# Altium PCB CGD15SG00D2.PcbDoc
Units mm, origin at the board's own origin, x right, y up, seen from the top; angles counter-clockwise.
Board outline 47.62 x 17.78 mm, 4 copper layers (TOP, INNER1, INNER2, BOTTOM), stack 1.557 mm thick; 46 components, 23 nets, 113 pads, 36 vias.
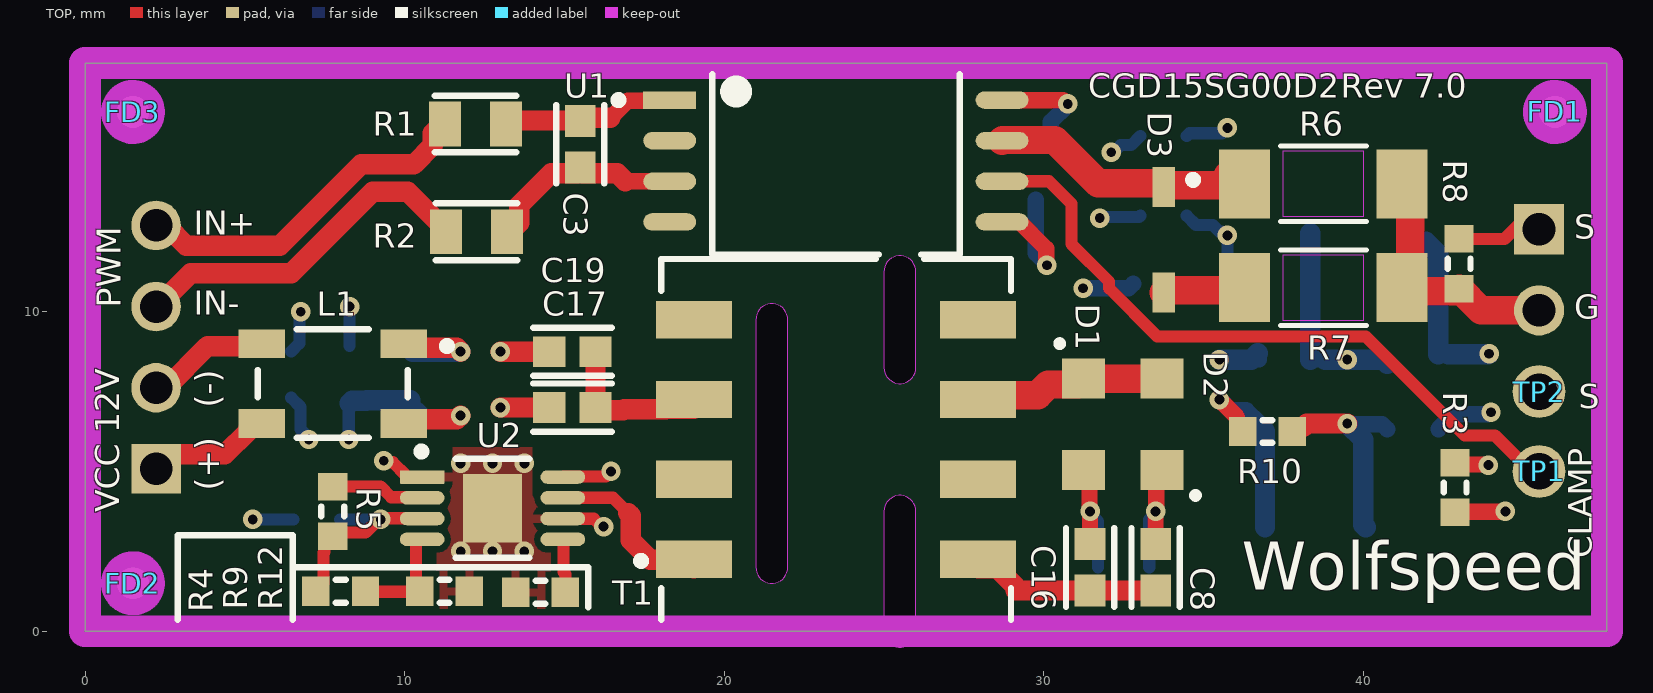
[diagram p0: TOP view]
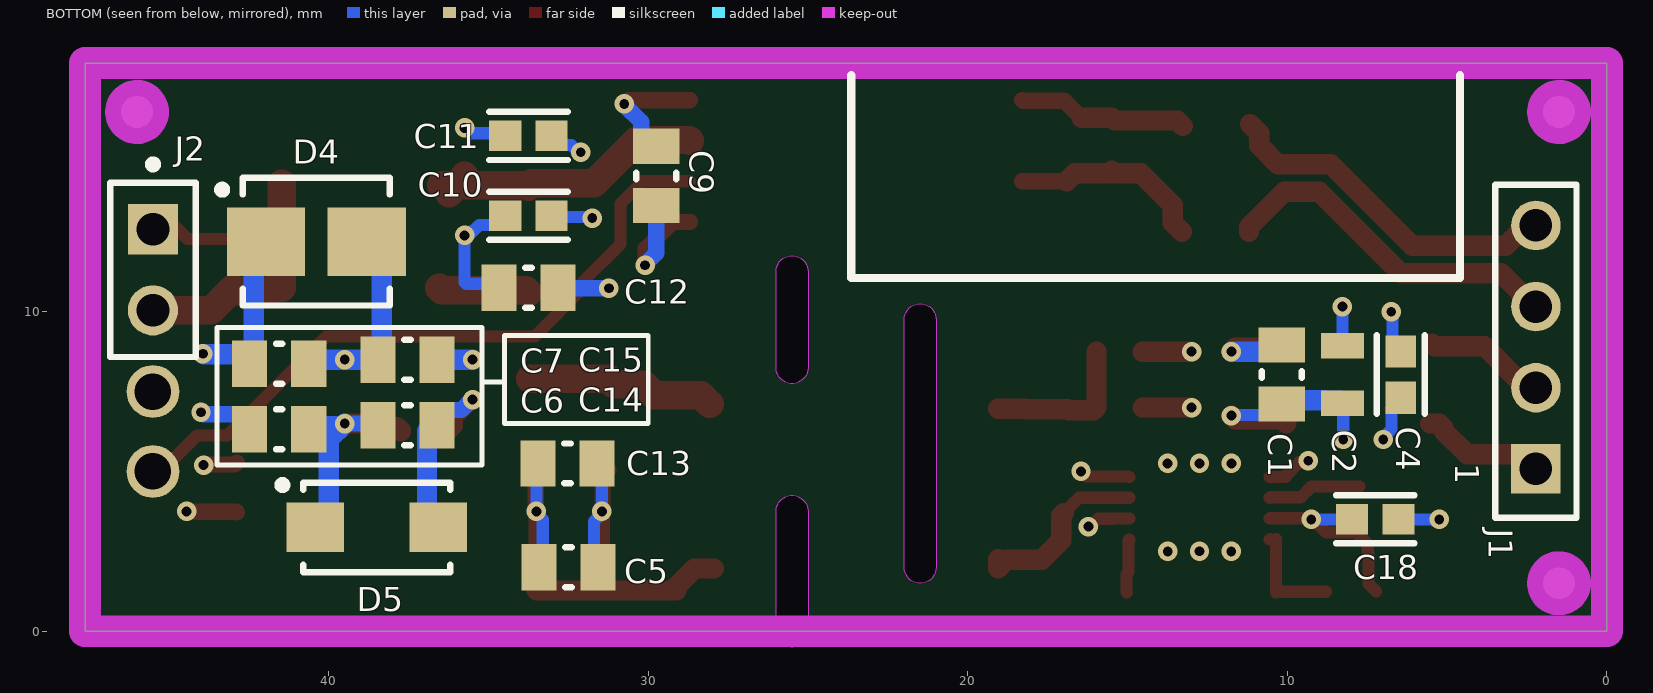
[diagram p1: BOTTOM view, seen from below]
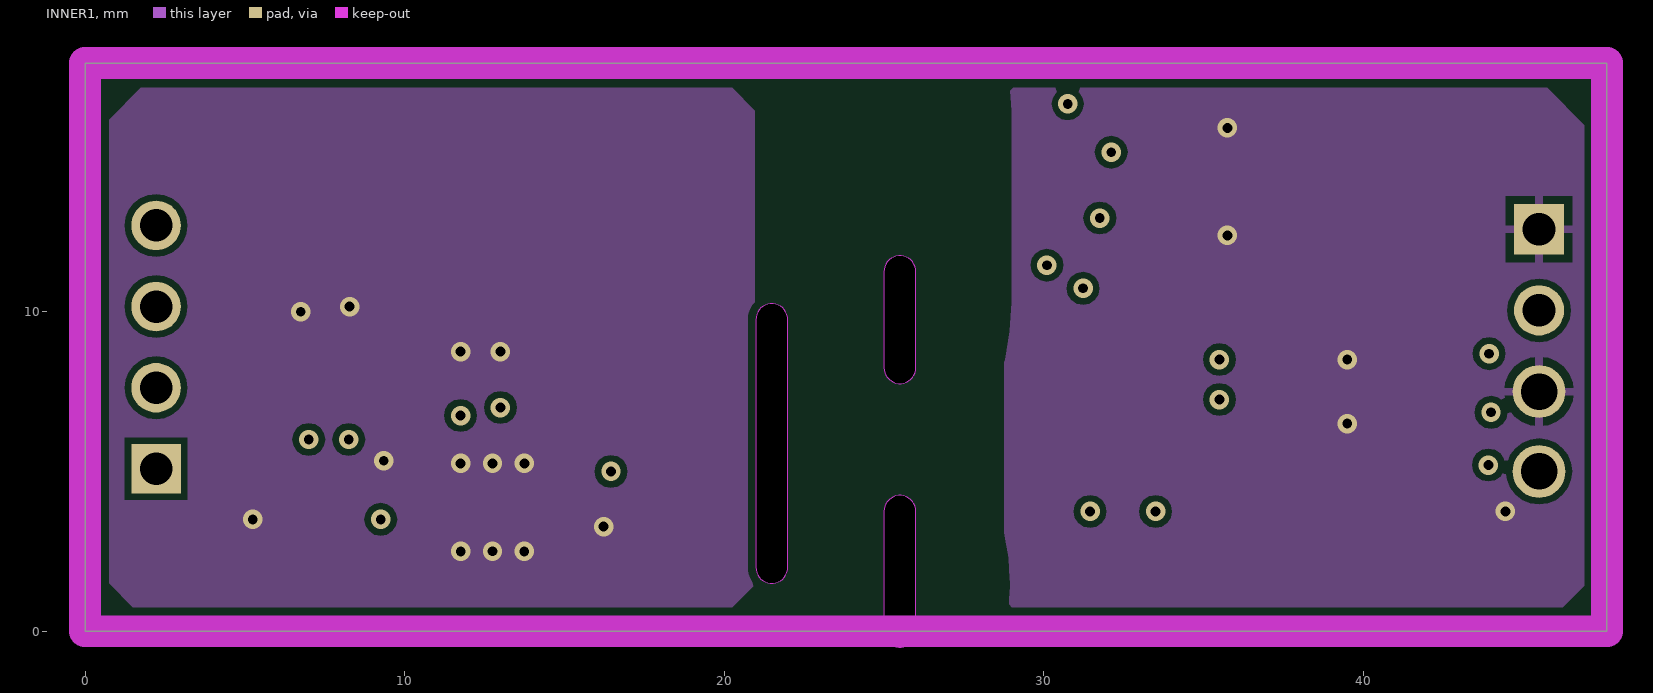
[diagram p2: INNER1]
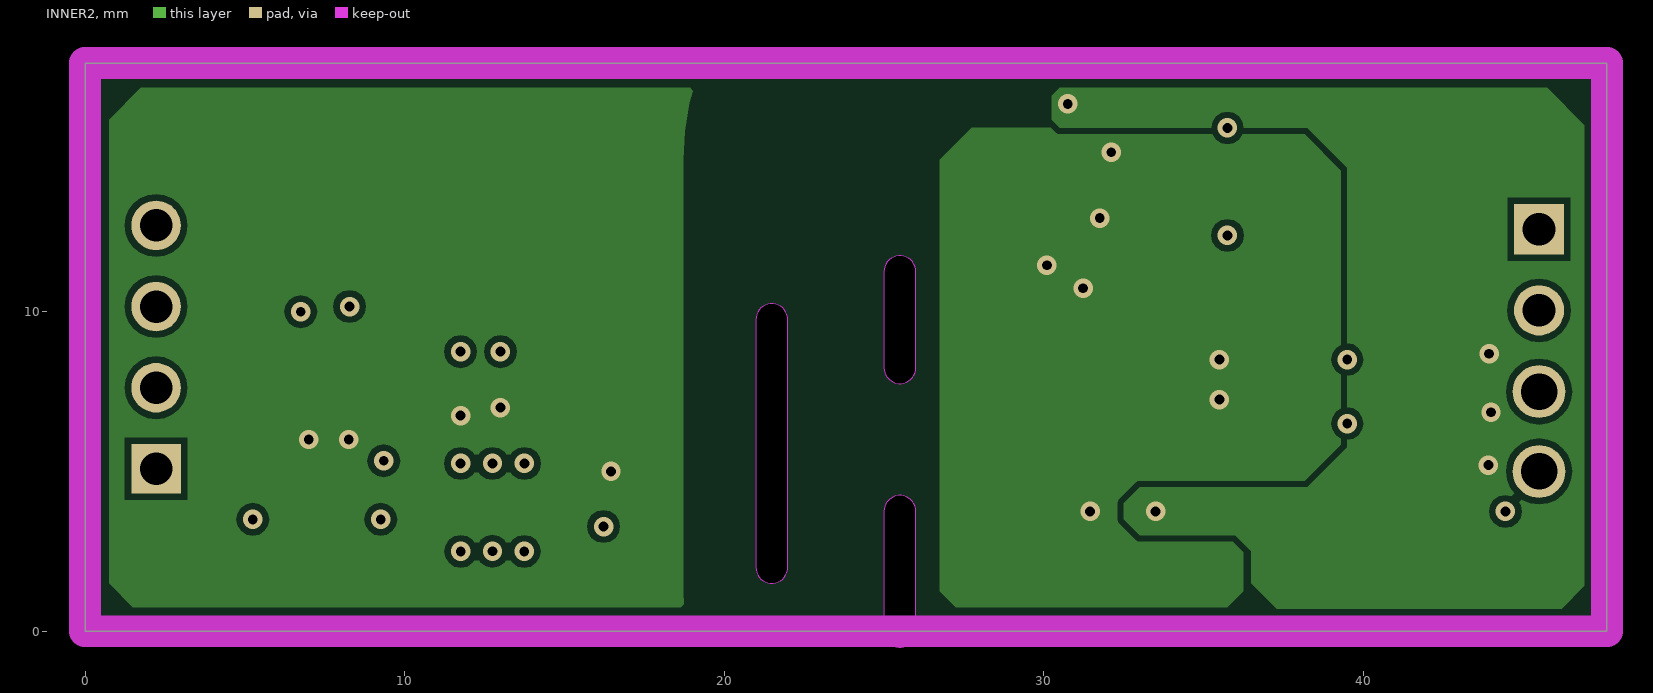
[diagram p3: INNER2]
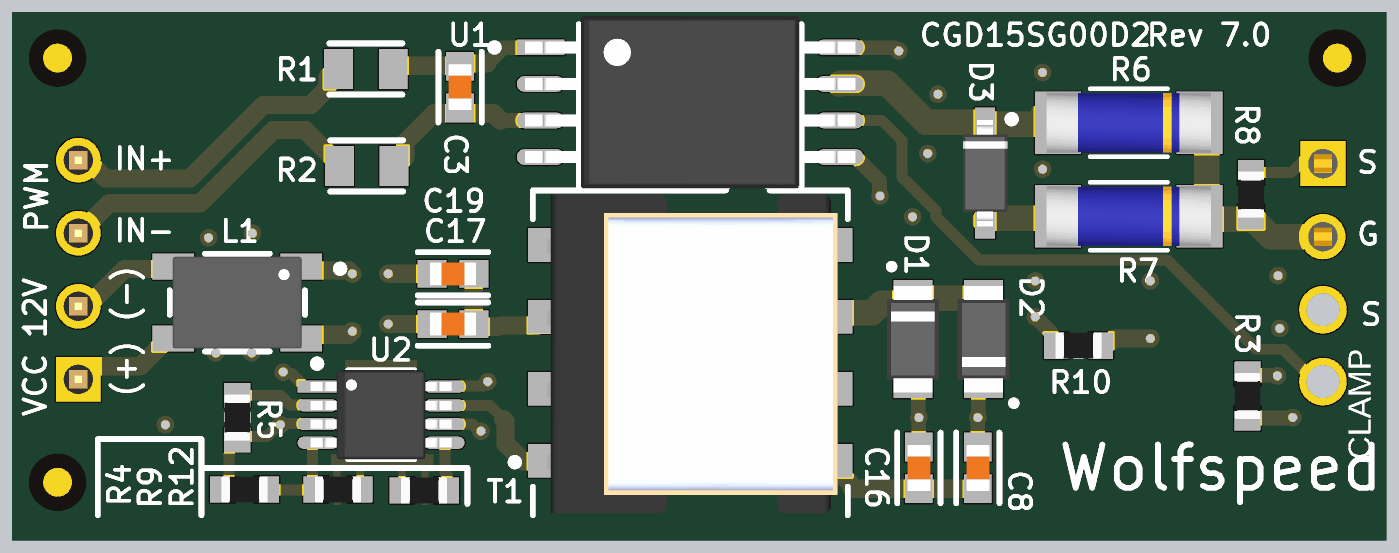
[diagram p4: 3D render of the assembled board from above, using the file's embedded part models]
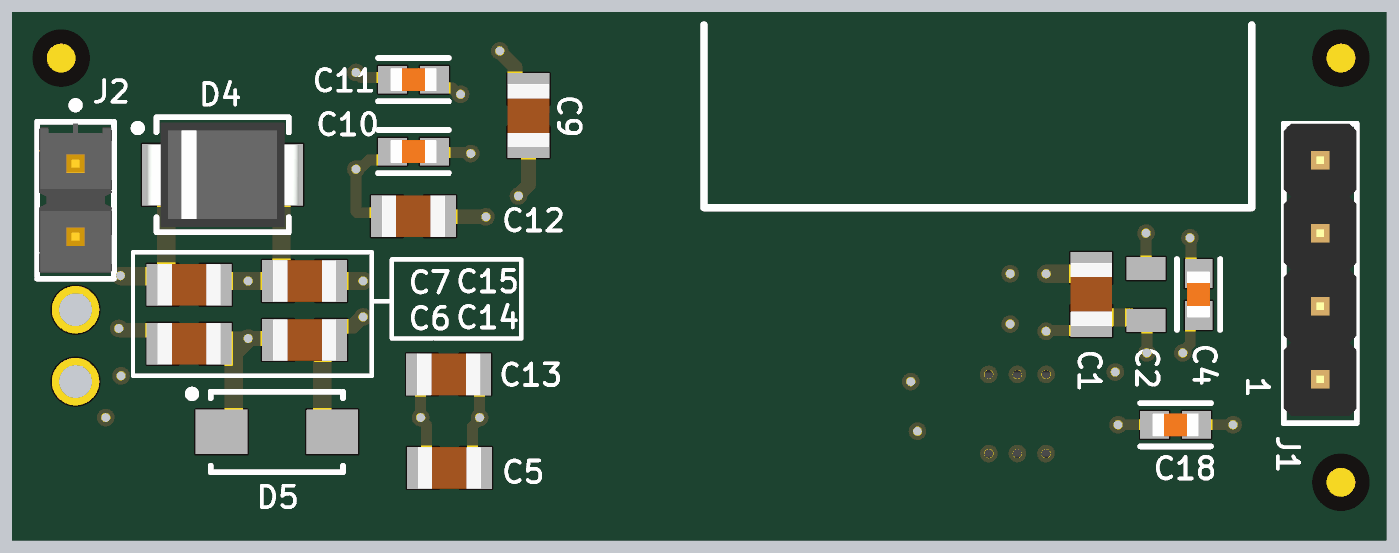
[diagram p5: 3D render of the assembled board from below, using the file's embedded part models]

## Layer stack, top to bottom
Top Solder: solder mask 0.0102, Solder Resist, Dk 3.5
TOP: signal copper 0.035
Dielectric 2: prepreg 0.1168, PP-016, Dk 4.4
Dielectric 1: prepreg 0.0965, PP-013, Dk 4.3
INNER1: signal copper 0.035
Dielectric2: core 0.9906, Core-042, Dk 4.6
INNER2: signal copper 0.035
Dielectric3: prepreg 0.0965, PP-013, Dk 4.3
Dielectric 3: prepreg 0.1168, PP-016, Dk 4.4
BOTTOM: signal copper 0.035
Bottom Solder: solder mask 0.0102, Solder Resist, Dk 3.5

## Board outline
47.625,17.78 0,17.78 0,0 47.625,0
cut-out: 25,0 ccw(c25.5,0) 26,0 26,3.75 ccw(c25.5,3.75) 25,3.75
cut-out: 25,8.25 ccw(c25.5,8.25) 26,8.25 26,11.25 ccw(c25.5,11.25) 25,11.25
cut-out: 20.99,2 ccw(c21.49,2) 21.99,2 21.99,9.75 ccw(c21.49,9.75) 20.99,9.75

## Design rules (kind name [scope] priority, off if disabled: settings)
BoardOutlineClearance [All] p1: gap=0.254 ignorepadtopadclearanceinfootprint=FALSE except(0: Arc-SplitContinuation Track-SplitContinuation SMDPad-SplitContinuation THPad-SplitContinuation Via-SplitContinuation Fill-SplitContinuation Poly-SplitContinuation Region-SplitContinuation Text-SplitContinuation; 0.2: Text-OutlineEdge Text-CavityEdge Text-CutoutEdge Text-SplitBarrior)
Clearance "Clearance No Connect Pins" [InPadClass('No Connect')] p1: gap=0.254 ignorepadtopadclearanceinfootprint=FALSE
Clearance Clearance_HV_Outer [InLayerClass('External')AND InNetClass('HV') vs InLayerClass('External')AND InNetClass('LV')] p2: gap=6.5 ignorepadtopadclearanceinfootprint=FALSE
Clearance [All] p3: gap=0.198 ignorepadtopadclearanceinfootprint=FALSE
ComponentClearance [All] p1: gap=0 collisioncheckmode=3 verticalgap=0 showdistances=FALSE
Creepage [InNetClass('HV') vs InNetClass('LV')] p1: checkdistance=8 applytopolygonpour=TRUE
HoleSize [All] p1: absolutevalues=TRUE maxlimit=6.35 minlimit=0.254 maxpercent=80.000 minpercent=20.000
MinimumSolderMaskSliver [All] p1: minsoldermaskwidth=0.102
PolygonConnect [All] p1: connectstyle=Relief reliefconductorwidth=0.254 reliefentries=4 polygonreliefangle="90 Angle" airgapwidth=0.254
RoomDefinition Primary [InComponentClass('Primary')] p1: confinementstyle=ConfineIn formatcopy=TRUE lockcomponents=FALSE outline 0,0 21.679,0 21.679,17.78 0,17.78
RoutingVias [All] p1: holewidth=0.305 width=0.61 viastyle="Through Hole" minholewidth=0.254 minwidth=0.61 maxholewidth=0.635 maxwidth=1.27
SilkToSilkClearance [All] p1: silktosilkclearance=0.127
SilkToSolderMaskClearance [IsPad] p1: minsilkscreentomaskgap=0.051 clearancetoexposedcopper=TRUE
SolderMaskExpansion [All] p1: expansion=0.051 istentingtop=FALSE
SupplyNets "Schematic Supply Nets_6" [InNet('+12V_O')] p1: voltage=0.000
SupplyNets "Schematic Supply Nets_5" [InNet('+12V_PWR')] p2: voltage=0.000
SupplyNets "Schematic Supply Nets_4" [InNet('SOURCE')] p3: voltage=0.000
SupplyNets "Schematic Supply Nets_3" [InNet('GND_SIGNAL')] p4: voltage=0.000
SupplyNets "Schematic Supply Nets_2" [InNet('VDD2')] p5: voltage=0.000
SupplyNets "Schematic Supply Nets_1" [InNet('VSS2')] p6: voltage=0.000
SupplyNets "Schematic Supply Nets" [InNet('PGND')] p7: voltage=0.000
Width [All] p1: maxlimit=1.27 minlimit=0.254 preferedwidth=0.635
25 further rules are at their usual default settings.

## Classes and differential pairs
pad class "No Connect": T1-2 T1-4 T1-5 T1-7 U1-2 U1-4
component class Primary: C1 C2 C4 C17 C18 C19 L1 R4 R5 R9 R12 U2
net class LV: +12V_O +12V_PWR GND_SIGNAL IN+ IN- NetC3_1 NetC3_2 NetC17_2 NetC18_1 NetR4_1 NetR5_1 NetR12_2 NetT1_1 PGND
net class HV: GATE NetC8_2 NetD1_1 NetD3_1 NetD3_2 NetTP1_1 SOURCE VDD2 VSS2
component class "Bias Supply": C1 C2 C4 C5 C6 C7 C8 C13 C14 C15 C16 C17 C18 C19 D1 D2 D4 D5 L1 R3 R4 R5 R9 R10 R12 T1 U2
component class "Gate Drive": .75 C3 C9 C10 C11 C12 D3 FD1 FD2 FD3 J1 J2 P1 R1 R2 R6 R7 R8 TP1 TP2 U1

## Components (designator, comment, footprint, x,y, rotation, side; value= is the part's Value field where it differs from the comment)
C1 "C2012X7R1V475K125AC" CAPC2012X15N 10.177,8.031 r90 bottom value=4.7µF
C2 "C2012X7R1V475K125AC" CAPC2012X15LB 8.277,8.031 r90 bottom value=4.7µF
C3 "C0C0603C103K5RAC7411" FP-C0603C-CF-IPC_B 15.494,15.24 r270 top value=10nF
C4 "C0C0603C103K5RAC7411" FP-C0603C-CF-IPC_B 6.451,8.031 r90 bottom value=10nF
C5 "C2012X7R1V475K125AC" CAPC2012X15N 32.5,2 r180 bottom value=4.7µF
C6 "C2012X7R1V475K125AC" CAPC2012X15N 41.55,6.318 r180 bottom value=4.7µF
C7 "C2012X7R1V475K125AC" CAPC2012X15N 41.55,8.368 r180 bottom value=4.7µF
C8 "CGA3E2X7R1H223K080AA" FP-C0603C-CF-IPC_B 33.5,2 r270 top value=22nF
C9 "C2012X7R1V475K125AC" CAPC2012X15N 29.75,14.25 r270 bottom value=4.7µF
C10 "C0C0603C103K5RAC7411" FP-C0603C-CF-IPC_B 33.75,13 r180 bottom value=10nF
C11 "CL10B104KB8NNWC" FP-C0603C-CF-IPC_B 33.75,15.5 r0 bottom value=100nF
C12 "C2012X7R1V475K125AC" CAPC2012X15N 33.75,10.75 r180 bottom value=4.7µF
C13 "C2012X7R1V475K125AC" CAPC2012X15N 32.527,5.25 r180 bottom value=4.7µF
C14 "C2012X7R1V475K125AC" CAPC2012X15N 37.536,6.45 r180 bottom value=4.7µF
C15 "C2012X7R1V475K125AC" CAPC2012X15N 37.536,8.5 r180 bottom value=4.7µF
C16 "CGA3E2X7R1H223K080AA" FP-C0603C-CF-IPC_B 31.45,2 r90 top value=22nF
C17 "C1608X7R1V105K080AE" FP-C0603C-CF-IPC_B 15.25,7 r0 top value=1µF
C18 "C1608X7R1V105K080AE" FP-C0603C-CF-IPC_B 7.25,3.5 r180 bottom value=1µF
C19 "C1608X7R1V105K080AE" FP-C0603C-CF-IPC_B 15.25,8.75 r180 top value=1µF
D1 "SL14PL-TP" WS_SOD123F_B 31.242,6.477 r270 top
D2 "SL14PL-TP" WS_SOD123F_B 33.7,6.477 r90 top
D3 "1N5819HW-7-F" WS_SOD123_B 33.75,12.25 r270 top
D4 "1SMB5929B-13" WFP-DO214AA/SMB_B 40.386,12.192 r180 bottom
D5 "1SMA5915BT3G" DO-214AC_SMA_B 38.5,3.25 r180 bottom
FD1 "FID1X2R Two Sided" FID1X2R 46,16.25 r0 top
FD2 "FID1X2R Two Sided" FID1X2R 1.5,1.5 r90 top
FD3 "FID1X2R Two Sided" FID1X2R 1.5,16.25 r90 top
J1 "TSW-104-07-G-S" TSW-104-07-G-S-Footprint-1 2.222,5.08 r90 bottom
J2 "TSW-102-07-G-S" FP-TSW-102-07-G-S-MFG 45.5,11.31 r270 bottom
L1 "DLW43SH220XK2L" FP-DLW43SH-MFG 7.75,7.75 r180 top value=22mH
R1 "CRCW0805121RFKTA" RESC2012X05N 12.221,15.871 r0 top value=121
R2 "CRCW0805121RFKTA" RESC2012X05N 12.25,12.5 r0 top value=121
R3 "RMCF0603FT20K0" FP-AC0603-IPC_B 42.875,4.5 r90 top value=20k
R4 "RT0603BRE075KL" FP-AC0603-IPC_B 8,1.25 r180 top value=5k
R5 "RG1608P-103-B-T5" FP-AC0603-IPC_B 7.75,3.75 r270 top value=10k
R6 "MMB02070C1009FB200" MELF0207_VIS 38.75,14 r0 top value=10
R7 "MMB02070C1009FB200" MELF0207_VIS 38.75,10.75 r0 top value=10
R8 "RMCF0603FT47K0" FP-AC0603-IPC_B 43,11.5 r270 top value=47k
R9 "RT0603BRE075KL" FP-AC0603-IPC_B 11.25,1.25 r180 top value=5k
R10 "RMCF0603FT5K10" FP-AC0603-IPC_B 37,6.25 r0 top value=5.1k
R12 "RMCF0603FT47K0" FP-AC0603-IPC_B 14.25,1.218 r0 top value=47k
T1 "750319177" 750319177-Footprint-1 23.5,6 r90 top
TP1 "CLAMP" "Test Point 25mil pin-Footprint-1" 45.5,5 r0 top net-tie
TP2 "Test Point 25mil pin" "Test Point 25mil pin-Footprint-1" 45.5,7.5 r0 top net-tie
U1 "UCC23514MDWVR" FP-DWV0008A-IPC_C 23.495,14.715 r0 top
U2 "UCC25800AQDGNQ1" WS_VSSOP-8_MFG 12.75,3.85 r0 top

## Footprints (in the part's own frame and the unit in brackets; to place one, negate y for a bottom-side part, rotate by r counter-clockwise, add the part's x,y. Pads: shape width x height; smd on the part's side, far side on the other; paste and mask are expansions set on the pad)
750319177-Footprint-1 [mm]
  rect 1.17x2.39 smd: 1(-3.75,4.445) 2(-1.25,4.445) 3(1.25,4.445) 4(3.75,4.445) 5(3.75,-4.445) 6(1.25,-4.445) 7(-1.25,-4.445) 8(-3.75,-4.445)
  silkscreen extent -5.65,-5.48 5.65,6.22, body extent -5.58,-5.11 5.55,5.05, height 11.56
CAPC2012X15LB [mm] "Chip Capacitor, 2-Leads, Body 2.00x1.25mm, IPC High Density"
  rect 0.8x1.35 smd: 1(-0.9,0) 2(0.9,0)
  body extent -1.1,-0.72 1.1,0.72, height 1.5
CAPC2012X15N [mm] "Chip Capacitor, 2-Leads, Body 2.00x1.25mm, IPC Medium Density"
  rect 1.1x1.45 smd: 1(-0.925,0) 2(0.925,0)
  silkscreen extent -0.1,-0.63 0.1,0.63, body extent -1.1,-0.72 1.1,0.72, height 1.1
DO-214AC_SMA_B [mm] "Molded Diode, 2-Leads, Body 4.25x2.59mm, IPC Medium Density"
  rect 1.8x1.55 smd: 1(-1.925,0) 2(1.925,0)
  silkscreen extent -3.08,-1.4 2.3,1.45, body extent -2.3,-1.4 2.3,1.39, height 2.29
FID1X2R [mm] "Fiducial - Round 1x2mm"
  round 1 smd far side paste-0.5 mask+0.5: 0(0,0)
  round 1 smd paste-0.5 mask+0.5: 0(0,0)
  TOP keep-out circle w1: c0,0 r0.5
  BOTTOM keep-out circle w1: c0,0 r0.5
FP-AC0603-IPC_B [mm]
  rect 0.859x0.912 smd paste+0: 1(-0.777,0) 2(0.777,0)
  silkscreen extent -0.15,-0.36 0.15,0.36, body extent -0.8,-0.45 0.8,0.45, height 0.5
FP-C0603C-CF-IPC_B [mm] "Chip Capacitor, 2-Leads, IPC Medium Density"
  rect 1.007x0.958 smd paste+0: 1(-0.726,0) 2(0.726,0)
  silkscreen extent -1.23,-0.75 1.23,0.75, body extent -0.8,-0.4 0.8,0.4, height 0.89
FP-DLW43SH-MFG [mm]
  rect 1.45x0.9 smd paste+0: 1(-2.225,-1.25) 2(2.225,-1.25) 3(2.225,1.25) 4(-2.225,1.25)
  silkscreen extent -3.7,-1.7 2.35,1.7, body extent -2.35,-1.7 2.35,1.7, height 2.8
FP-DWV0008A-IPC_C [mm] "SOIC-8W"
  rect 1.654x0.542 smd paste+0: 1(-5.201,1.905)
  rrect100% 1.654x0.542 smd paste+0: 2(-5.201,0.635) 3(-5.201,-0.635) 4(-5.201,-1.905) 5(5.201,-1.905) 6(5.201,-0.635) 7(5.201,0.635) 8(5.201,1.905)
  silkscreen extent -6.93,-2.93 3.87,2.71, body extent -5.75,-3 5.75,3, height 2.8
FP-TSW-102-07-G-S-MFG [mm]
  rect 1.57x1.57 hole 1.02 paste-2539.97: 1(-1.27,0)
  round 1.57 hole 1.02 paste-2539.97: 2(1.27,0)
  silkscreen extent -3.42,-1.34 2.73,1.34, body extent -2.67,-1.27 2.54,1.27, height 8.71
MELF0207_VIS [mil] "MELF0207"
  rect 63x85 smd paste+0: 1(-97,0) 2(97,0)
  TOP keep-out region: -49.21,-40.5 -49.21,40.5 49.21,40.5 49.21,-40.5
  silkscreen extent -53,-46 53,46, body extent -113,-41 113,41, height 83
RESC2012X05N [mm] "Chip Resistor, 2-Leads, Body 2.05x1.25mm, IPC Medium Density"
  rect 1x1.4 smd: 1(-0.95,0) 2(0.95,0)
  silkscreen extent -1.27,-0.89 1.27,0.89, body extent -1.1,-0.7 1.1,0.7, height 0.5
"Test Point 25mil pin-Footprint-1" [mil]
  round 65 hole 45: 1(0,0)
TSW-104-07-G-S-Footprint-1 [mm] "HEADER_4X1_100"
  rect 1.55x1.55 hole 1.02: 1(0,0)
  round 1.55 hole 1.02: 2(2.54,0) 3(5.08,0) 4(7.62,0)
  silkscreen extent -1.52,-1.27 8.89,1.27, body extent -1.27,-1.27 8.89,1.27, height 8.38
WFP-DO214AA/SMB_B [mm] "DO214AA/SMB Diode Level B - medium density"
  rect 2.45x2.15 smd: 1(-1.575,0) 2(1.575,0)
  silkscreen extent -3.08,-2 2.3,2, body extent -2.65,-1.97 2.65,1.97, height 2.5
WS_SOD123_B [mm] "SOD123 Level B - medium density"
  rect 1.257x0.702 smd paste+0: 1(-1.65,0) 2(1.65,0)
  silkscreen extent -2,0.8 -1.75,1.05, body extent -1.85,-0.85 1.85,0.85, height 1.35
WS_SOD123F_B [mm] "SOD123F Level B - medium density"
  rect 1.25x1.35 smd: 1(-1.425,0) 2(1.425,0)
  silkscreen extent -2.62,-0.84 -2.42,-0.64, body extent -1.85,-0.95 1.85,0.95, height 1.15
WS_VSSOP-8_MFG [mm] "VSSOP-8 TI datasheet footprint"
  rrect10% 1.4x0.42 smd mask+0.05: 1(-2.2,0.975)
  oval 1.4x0.42 smd mask+0.05: 2(-2.2,0.325) 3(-2.2,-0.325) 4(-2.2,-0.975) 5(2.2,-0.975) 6(2.2,-0.325) 7(2.2,0.325) 8(2.2,0.975)
  rect 1.85x2.15 smd: 9(0,0)
  silkscreen extent -2.35,-1.55 1.15,1.9, body extent -2.45,-1.55 2.45,1.55, height 1.1

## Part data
C1 C2 C5 C6 C7 C9 C12 C13 C14 C15: library part CMP-00012-10, "C Series 0805 4.7 uF 35 V ±10 % Tolerance X7R SMT Multilayer Ceramic Capacitor", Capacitor Type=Ceramic, Case Code (Imperial)=0805, Case Code (Metric)=2012, Dielectric=X7R, Max Operating Temperature=125°C, Min Operating Temperature=-55°C, Package Quantity=2000, Tolerance=10%, Voltage Rating=35V
C3 C4 C10: library part CMP-001-00092-25, "Ceramic Capacitor, Multilayer, Ceramic, 50V, 10% +Tol, 10% -Tol, X7R, 15% TC, 0.01uF, Surface Mount, 0603", Capacitor Type=Ceramic, Case/Package=0603, Max Operating Temperature=125°C, Min Operating Temperature=-55°C, Temperature Coefficient=X7R, Tolerance=10%, Voltage Rating=50V
C8 C16: library part CMP-001-00120-23, "Ceramic Capacitor, Multilayer, Ceramic, 50V, 10% +Tol, 10% -Tol, X7R, 15% TC, 0.022uF, Surface Mount, 0603", Capacitor Type=Ceramic, Case/Package=0603, Max Operating Temperature=125°C, Min Operating Temperature=-55°C, Temperature Coefficient=X7R, Tolerance=10%, Voltage Rating=50V
C11: library part CMP-00017-19, "CAP CER 0.1UF 50V X7R 0603", Capacitor Type=Ceramic, Case/Package=0603, Max Operating Temperature=125°C, Min Operating Temperature=-55°C, Temperature Coefficient=X7R, Tolerance=10%, Voltage Rating=50V
C17 C18 C19: library part CMP-001-00097-24, "Ceramic Capacitor, Multilayer, Ceramic, 35V, 10% +Tol, 10% -Tol, X7R, 15% TC, 1uF, Surface Mount, 0603", Capacitor Type=Ceramic, Case/Package=0603, Max Operating Temperature=125°C, Min Operating Temperature=-55°C, Temperature Coefficient=X7R, Tolerance=10%, Voltage Rating=35V
D1 D2: library part CMP-004-00061-8, "Diode Schottky 40V 1A SOD123FL", Case/Package=SOD-123, Forward Current=1A, Forward Voltage=400mV, Max Operating Temperature=150°C, Min Operating Temperature=-55°C
D3: library part CMP-004-00065-7, "DIODE SCHOTTKY 40V 1A SOD123", Case/Package=SOD123, Forward Current=1A, Forward Voltage=450mV, Max Operating Temperature=125°C, Min Operating Temperature=-65°C
D4: library part CMP-004-00077-2, "Zener Diode, 15V V(Z), 5%, 0.55W, Silicon, Unidirectional", Case/Package=SMB, Max Operating Temperature=150°C, Min Operating Temperature=-65°C, Zener Voltage=15V
D5: library part CMP-004-00074-8, "Zener Diodes 3.9V 1.5W", Case/Package=SMA, Forward Voltage=1.5V, Max Operating Temperature=150°C, Min Operating Temperature=-65°C
FD1 FD2 FD3: library part CMP-00028-00054-1, "Fiducial - Round 1x2mm"
J1: library part CMP-002-00219-2, "Conn Unshrouded Header HDR 4 POS 2.54mm Solder ST Top Entry Thru-Hole Bag", Max Operating Temperature=125°C, Min Operating Temperature=-55°C
J2: library part CMP-002-00128-3, "CONN HEADER 2POS .100 SGL GOLD", Case/Package="Pin Header, Male", Max Operating Temperature=125°C, Min Operating Temperature=-55°C
L1: library part CMP-006-00046-3, "Ind Common Mode Choke Unshielded Wirewound 22uH -30%/+50% 100kHz Ferrite 310mA T/R", Case/Package=1812, Max Operating Temperature=125°C, Min Operating Temperature=-40°C, Tolerance=50%
R1 R2: library part CMP-009-00308-2, "Fixed Resistor, Metal Glaze/thick Film, 0.125W, 121ohm, 150V, 1% +/-Tol, 100ppm/Cel, Surface Mount, 0805", Case/Package=0805, Max Operating Temperature=155°C, Min Operating Temperature=-55°C, Power=125mW, Tolerance=1%
R3: library part CMP-009-00039-7, "Fixed Resistor, Metal Glaze/thick Film, 0.1W, 20000ohm, 75V, 1% +/-Tol, 100ppm/Cel, Surface Mount, 0603", Case/Package=0603, Max Operating Temperature=155°C, Min Operating Temperature=-55°C, Power=100mW, Tolerance=1%, Voltage Rating=75V
R4 R9: library part CMP-009-00265-3, "Fixed Resistor, Thin Film, 0.1W, 5000ohm, 75V, 0.1% +/-Tol, 50ppm/Cel, Surface Mount, 0603", Case/Package=0603, Max Operating Temperature=155°C, Min Operating Temperature=-55°C, Power=100mW, Temperature Coefficient=50ppm/°C, Tolerance=0.1%
R5: library part CMP-009-00206-6, "Res SMD 10K Ohm 0.1% 1/10W 0603", Case/Package=0603, Max Operating Temperature=155°C, Min Operating Temperature=-55°C, Power=100mW, Tolerance=0.1%, Voltage Rating=75V
R6 R7: library part CMP-009-00258-2, "Res Thin Film 0207 10 Ohm 1% 2/5W ±50ppm/°C Conformal Melf SMD Blister T/R", Case/Package=MELF0207, Max Operating Temperature=155°C, Min Operating Temperature=-55°C, Power=1W, Tolerance=1%, Voltage Rating=200V
R8 R12: library part CMP-009-00042-7, "Fixed Resistor, Metal Glaze/thick Film, 0.1W, 47000ohm, 75V, 1% +/-Tol, 100ppm/Cel, Surface Mount, 0603", Case/Package=0603, Max Operating Temperature=155°C, Min Operating Temperature=-55°C, Power=100mW, Tolerance=1%, Voltage Rating=75V
R10: library part CMP-009-00011-7, "Fixed Resistor, Metal Glaze/thick Film, 0.1W, 5100ohm, 75V, 1% +/-Tol, 100ppm/Cel, Surface Mount, 0603", Case/Package=0603, Max Operating Temperature=155°C, Min Operating Temperature=-55°C, Power=100mW, Tolerance=1%, Voltage Rating=75V
T1: library part CMP-012-00002-6, "WE-AGDT Auxiliary Gate Drive", Max Operating Temperature=130°C, Min Operating Temperature=-40°C
TP1 TP2: library part CMP-017-000001-2, "Test Point"
U1: library part CMP-00024-00033-4, "4-A, 12-V UVLO 5-KVrms opto compatible single channel gate driver with miller clamp and split output 8-SOIC -40 to 125", Case/Package=SOIC-8W, Max Operating Temperature=150°C, Min Operating Temperature=-40°C
U2: library part CMP-019-00091-5, "Open-loop LLC transformer driver for isolated bias supplies 8-HVSSOP -40 to 125", Case/Package=8-TSSOP, Max Supply Voltage=34V, Min Supply Voltage=9V

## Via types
v1: diameter 0.61, hole 0.305, TOP to BOTTOM, tented both sides, 36 vias

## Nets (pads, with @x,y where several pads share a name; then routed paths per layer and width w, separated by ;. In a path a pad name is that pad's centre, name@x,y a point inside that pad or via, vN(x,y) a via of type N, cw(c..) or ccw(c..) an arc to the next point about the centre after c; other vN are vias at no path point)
+12V_O: J1.1 L1.3 | length 3.9
  TOP w0.635: J1.1 2.68,5.537 4.375,5.537 5.118,6.28 5.118,6.367 5.25,6.5 L1.3
+12V_PWR: C1.1 C2.1 C4.1 C17.1 L1.4 U2.8 | length 11.3
  TOP w0.381: U2.8 14.969,4.844 16.302,4.844 v1(16.458,5)
  TOP w0.635: L1.4@10.025,6.5 10.158,6.633 11.633,6.633 v1(11.75,6.75) ; v1(13,7) C17.1
  BOTTOM w0.381: C4.1 6.74,7.017 6.74,6.322 7,6.062 v1(7,6) ; v1(8.25,6) 8.25,7.104 C2.1 ; C1.1@10.177,7.231 10.636,6.771 11.729,6.771 v1(11.75,6.75)
  BOTTOM w0.635: C2.1 8.359,7.213 8.799,7.213 8.817,7.231 C1.1@10.177,7.231
GATE: J2.2 R6.2 R7.2 R8.2 | length 7.9
  TOP w0.889: R7.2@41.464,10.75 R6.2@41.464,14 ; R7.2@41.464,10.998 41.819,10.642 R8.2@43,10.642 ; R8.2 43.683,10.04 J2.2@45.664,10.04
GND_SIGNAL: J1.2 L1.2 | length 3.8
  TOP w0.635: J1.2@2.286,7.62 2.534,7.62 3.831,8.917 5.392,8.917 L1.2@5.475,9
IN+: J1.4 R1.1 | length 10.9
  TOP w0.635: J1.4@2.286,12.7 2.534,12.7 3.169,12.065 6.094,12.065 8.646,14.617 10.294,14.617 10.884,15.207 10.884,15.585 R1.1@11.17,15.871
IN-: J1.3 R2.1 | length 11
  TOP w0.635: J1.3@2.286,10.16 2.286,10.186 3.301,11.201 6.451,11.201 9.003,13.753 10.097,13.753 11.199,12.651 R2.1@11.199,12.5
NetC3_1: C3.1 R1.2 U1.1 | length 5.4
  TOP w0.508: 16.446,16.065 16.984,16.603 18.277,16.603 U1.1
  TOP w0.635: R1.2@13.271,15.81 13.444,15.982 15.411,15.982 15.494,16.065 16.446,16.065
NetC3_2: C3.2 R2.2 U1.3 | length 6.2
  TOP w0.508: 16.908,14.08 U1.3
  TOP w0.635: R2.2@13.301,12.5 13.587,12.786 13.587,13.333 14.586,14.332 15.411,14.332 15.494,14.415 15.577,14.332 16.656,14.332 16.908,14.08
NetC8_2: C8.2 C16.1 T1.8 | length 5.9
  TOP w0.635: T1.8@27.94,1.965 28.55,1.965 29.114,1.401 29.114,1.274 C16.1 C8.2
NetC17_2: C17.2 C19.1 T1.3 | length 4.9
  TOP w0.635: C19.1 C17.2 16.064,6.912 16.838,6.912 16.875,6.949 18.172,6.949 18.189,6.965 T1.3@19.05,6.965
NetC18_1: C18.1 R4.2 R5.2 U2.3 | length 6.3
  TOP w0.381: R4.2 7.462,1.489 7.462,2.462 7.484,2.484 7.484,2.734 7.723,2.973 R5.2 7.865,3.088 8.776,3.088 9.188,3.5 v1(9.25,3.5) 9.287,3.537 10.53,3.537 10.538,3.537 U2.3
  BOTTOM w0.381: C18.1 v1(9.25,3.5)
NetD1_1: D1.1 D2.2 T1.6 | length 5.9
  TOP w0.889: T1.6@28.081,7.11 28.362,7.391 29.813,7.391 30.144,7.722 31.061,7.722 D1.1 D2.2
NetD3_1: D3.1 R6.1 U1.7 | length 9.2
  TOP w0.889: U1.7 28.719,15.373 30.347,15.373 31.707,14.013 33.657,14.013 33.75,13.919 D3.1 33.8,13.95 R6.1@36.486,13.95 ; R6.1@35.75,14.25 R6.1@36.236,13.7
NetD3_2: D3.2 R7.1 | length 2.8
  TOP w0.889: D3.2 33.825,10.675 36.461,10.675 R7.1@36.536,10.75
NetR4_1: R4.1 R9.2 U2.4 | length 3.3
  TOP w0.381: R4.1@8.792,1.234 10.345,1.234 10.361,1.218 U2.4@10.361,2.887 ; U2.4@10.538,2.887 U2.4
NetR5_1: R5.1 U2.2 | length 2.9
  TOP w0.381: R5.1 9.247,4.527 9.58,4.194 10.53,4.194 U2.2
NetR12_2: R12.2 U2.5 | length 1.7
  TOP w0.381: U2.5 14.969,2.855 14.969,1.85 15.038,1.782 15.038,1.23 R12.2
NetT1_1: T1.1 U2.7 | length 5.8
  TOP w0.381: U2.7 16.524,4.175 17,3.699
  TOP w0.635: 17,3.699 17.075,3.624 17.075,2.84 17.683,2.232 18.782,2.232 19.05,1.965 19.05,2.245 T1.1
NetTP1_1: TP1.1 U1.6 | length 21.5
  TOP w0.381: U1.6 30.167,14.08 30.869,13.378 30.869,12.113 32.047,10.935 32.047,10.73 33.553,9.224 40.077,9.224 43.176,6.125 44.124,6.125 TP1.1@45.499,4.749
PGND: C1.2 C2.2 C4.2 C18.2 C19.2 L1.1 R9.1 R12.1 U2.1 U2.6 U2.9 | length 11.6
  TOP w0.381: v1(9.346,5.332) 9.389,5.289 9.628,5.289 10.04,4.876 10.04,4.844 10.06,4.825 U2.1 ; U2.6 15.451,3.525 15.457,3.519 15.919,3.519 16.163,3.275 v1(16.225,3.275)
  TOP w0.635: L1.1@10.025,9 10.158,8.867 11.633,8.867 v1(11.75,8.75) ; v1(13,8.75) C19.2
  BOTTOM w0.381: v1(5.25,3.5) C18.2 ; C4.2 6.706,9.012 6.706,9.956 v1(6.75,10) ; C2.2 v1(8.277,10.16)
  BOTTOM w0.635: C1.2@10.177,8.831 10.258,8.75 v1(11.75,8.75)
  other v1: 11.757,2.498 12.75,2.5 13.743,2.498 11.75,5.25 12.75,5.25 13.75,5.25
SOURCE: C6.2 C7.2 C10.1 C11.2 C12.1 C14.1 C15.1 D4.2 D5.1 J2.1 R3.1 R8.1 R10.2 TP2.1 | length 23.9
  TOP w0.381: R8.1 44.416,12.277 J2.1@45.11,12.971
  TOP w0.508: R3.1 42.888,3.737 44.437,3.737 v1(44.45,3.75)
  TOP w0.635: R10.2@37.75,6.25 37.75,6.277 37.862,6.389 38.122,6.389 38.234,6.5 v1(39.5,6.5)
  BOTTOM w0.381: C10.1 34.764,12.711 35.289,12.711 35.5,12.5 35.575,12.5 35.688,12.387 v1(35.75,12.387) 35.75,10.923 35.7,10.873 34.673,10.873 C12.1@34.55,10.75 ; C11.2 34.557,15.581 35.581,15.581 v1(35.75,15.75)
  BOTTOM w0.508: C14.1@38.336,6.45 38.386,6.5 v1(39.5,6.5) ; C15.1@38.336,8.5 C15.1@38.805,8.5 ; v1@39.519,6.481 40.587,6.481 C6.2@40.75,6.318
  BOTTOM w0.635: C15.1@38.336,8.5 D4.2@38.336,12.462 ; C15.1@38.805,8.5 v1(39.5,8.5) 40.618,8.5 C7.2@40.75,8.368 ; v1(39.5,6.5) 39.519,6.481 40,6 40,3.325 D5.1@40.075,3.25
VDD2: C5.1 C6.1 C7.1 C8.1 C9.1 C13.1 D2.1 D4.1 R3.2 U1.8 | length 17.4
  TOP w0.508: U1.8 28.702,16.614 30.609,16.614 30.723,16.5 v1(30.75,16.5) ; C8.1 v1(33.5,3.75) 33.519,3.769 33.519,4.871 D2.1 ; R3.2 42.931,5.22 43.897,5.22 v1(43.917,5.201)
  BOTTOM w0.381: C5.1@33.3,2 33.3,3.488 33.5,3.688 v1(33.5,3.75) 33.5,5.077 C13.1@33.327,5.25
  BOTTOM w0.508: C9.1@29.973,15.198 30.221,15.446 30.221,15.944 30.731,16.453 v1@30.731,16.468 ; C6.1@42.35,6.318 42.35,6.331 42.746,6.727 42.746,6.789 43.909,6.789 43.969,6.849 v1(43.997,6.849)
  BOTTOM w0.635: D4.1 42.35,11.803 C7.1@42.35,8.668 ; C7.1@42.65,8.668 43.406,8.668 v1@43.918,8.668
  other v1: 43.937,8.687
VSS2: C5.2 C9.2 C10.2 C11.1 C12.2 C13.2 C14.2 C15.2 C16.2 D1.2 D5.2 R10.1 U1.5 | length 23.1
  TOP w0.508: U1.5 29.242,12.81 30.08,11.973 30.08,11.475 v1(30.099,11.455) ; D1.2 31.43,4.864 31.43,3.769 v1(31.45,3.75) C16.2 ; v1(35.5,7.25) 36.048,6.702 36.048,6.425 R10.1
  BOTTOM w0.381: C5.2@31.7,2 31.7,3.438 31.45,3.688 v1(31.45,3.75) 31.45,4.973 C13.2@31.727,5.25 ; v1(31.757,12.929) 31.789,12.961 32.985,12.961 C10.2 ; v1(32.112,14.991) 32.156,15.034 32.23,15.034 32.407,15.211 32.736,15.211 C11.1
  BOTTOM w0.508: C9.2@29.75,13.5 29.75,13.45 29.75,11.832 30.099,11.483 v1(30.099,11.455) ; v1(31.229,10.729) 32.657,10.729 C12.2@32.8,10.873 ; v1(35.5,7.25) 35.527,7.25 35.857,6.921 36.34,6.921 36.736,6.525 C14.2@36.736,6.45 ; v1(35.5,8.5) C15.2@36.736,8.5
  BOTTOM w0.635: v1(35.5,8.5) 36.5,8.5 C15.2@36.695,8.695 ; C14.2@36.736,6.45 36.925,6.261 D5.2@36.925,3.25
pads on no net: FD1.0 FD2.0 FD3.0 T1.2 T1.4 T1.5 T1.7 U1.2 U1.4

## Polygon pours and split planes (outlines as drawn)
PGND on INNER1 "-" (solid, pour order 10): 0.75,1.5 0.75,16 1.75,17 20.25,17 20.955,16.295 20.955,1.455 20.25,0.75 1.5,0.75
SOURCE on INNER1 "INNER1-SOURCE" (solid, pour order 11): 26.75,16.25 26.75,1.25 27.25,0.75 46.25,0.75 47,1.5 47,15.75 45.75,17 27.5,17
+12V_PWR on INNER2 "-" (solid, pour order 13): 0.75,1.5 0.75,16 1.75,17 20.25,17 20.955,16.295 20.955,1.455 20.25,0.75 1.5,0.75
VDD2 on INNER2 "INNER2--3.3V" (solid, pour order 9): 30.5,15.75 38.25,15.75 39.5,14.5 39.5,5.75 38.25,4.5 33,4.5 32.5,4 32.5,3.5 33,3 36,3 36.5,2.5 36.5,1.5 38,0 45.5,0 47.625,2.125 47.625,15.125 45.75,17 30.5,17 30.25,16.75 30.25,16
VSS2 on INNER2 "INNER2--3.3V" (solid, pour order 12): 27.75,15.75 39.75,15.75 39.75,2.75 36.25,2.75 36.25,1.25 35.75,0.75 27.25,0.75 26.75,1.25 26.75,14.75
PGND on TOP "NONET_L-01_P-001" (solid, pour order 14): 14,4.25 14,5.75 11.5,5.75 11.5,5.25 11,5.25 11,0 15.5,0 15.5,4.25

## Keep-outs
Keep-Out Layer:
  lines w1: 0,0 0,0 ; 0,0 47.625,0 47.625,17.78 0,17.78 0,0

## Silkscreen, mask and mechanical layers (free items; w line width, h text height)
Top Overlay:
  lines w0.203: 2.9,0.356 2.9,3 3.798,3 4.181,3 4.447,3 5.33,3 6.5,3 6.5,2 ; 6.5,0.356 6.5,2 ; 15.75,0.75 15.75,2 6.5,2
  text "CGD15SG00D2" at 31.4,16.7 h0.75
  text "Rev 7.0" at 39.3,16.7 h0.75
  text "IN+" at 3.4,12.4 h0.75
  text "S" at 46.609,12.277 h0.75
  text "PWM" at 1.123,10.127 h0.75 r90
  text "IN-" at 3.4,9.9 h0.75
  text "G" at 46.609,9.779 h0.75
  text "(-)" at 4.2,7 h0.75 r90
  text "S" at 46.736,6.985 h0.75
  text "(+)" at 4.2,4.4 h0.75 r90
  text "VCC 12V" at 1.073,3.727 h0.75 r90
  text "Wolfspeed" at 36.2,1.3 h1.5
Bottom Overlay:
  lines w0.152: 35.2,7.8 34.5,7.8 34.5,9.25 ; 34.5,9.25 30,9.25 30,6.5 33,6.5 34.5,6.5 34.5,9.25 ; 35.2,5.2 43.5,5.2 43.5,9.5 35.2,9.5 35.2,5.2
  lines w0.254: 4.6,17.399 4.6,11.05 23.65,11.05 23.65,17.399
  text "1" at 4.75,5.25 h0.75 r90
Board Shape:
  lines w0.152: 20.987,2 ccw(c21.489,2.001) 21.99,2 21.99,9.75 ; 20.99,2 20.99,9.75 cw(c21.491,9.749) 21.993,9.75 ; 24.997,8.25 ccw(c25.499,8.251) 26,8.25 26,11.25 ; 25,0 25,3.75 cw(c25.501,3.749) 26.003,3.75 ; 25,8.25 25,11.25 cw(c25.501,11.249) 26.003,11.25 ; 26,0 26,3.75 ; 0,0 47.625,0 47.625,17.78 0,17.78 0,0
Sheet:
  lines w0.025: -89.535,-195.58 -89.535,83.82 342.265,83.82 342.265,-195.58 -89.535,-195.58
Sheet Format:
  lines w0.025: 202.565,45.72 202.565,53.34 202.565,76.2 ; 202.565,60.96 329.565,60.96 ; 202.565,68.58 329.565,68.58 ; 212.725,45.72 212.725,53.34 212.725,68.58 ; 222.885,-187.96 222.885,-142.24 329.565,-142.24 ; 222.885,-180.34 286.385,-180.34 ; 222.885,-170.18 329.565,-170.18 ; 222.885,-154.94 329.565,-154.94 ; 235.585,-180.34 235.585,-170.18 ; 245.745,-187.96 245.745,-180.34 ; 266.065,-180.34 266.065,-170.18 ; 281.305,45.72 281.305,53.34 ; 281.305,50.8 281.305,60.96 281.305,68.58 ; 286.385,-187.96 286.385,-180.34 ; 304.165,45.72 304.165,53.34 304.165,60.96 304.165,68.58 ; 329.565,-180.34 286.385,-180.34 ; -76.835,-187.96 -76.835,76.2 -74.295,76.2 329.565,76.2 329.565,45.72 329.565,-187.96 -76.835,-187.96
  text "REVISIONS" at 257.175,71.12 h0.75
  text "REV" at 203.835,63.5 h0.75
  text "DESCRIPTION" at 230.505,63.5 h0.75
  text "DATE" at 287.655,63.5 h0.75
  text "APPROVED" at 306.705,63.5 h0.75
  text "Wolfspeed" at 227.33,-146.685 h0.75
  text "Power Applications" at 226.695,-151.765 h0.75
  text "Discrete Gate Drive Board" at 256.54,-163.83 h0.75
  text "SIZE" at 224.155,-173.99 h0.75
  text "REVISION" at 237.49,-173.99 h0.75
  text "DWG NO" at 268.605,-173.99 h0.75
  text "B" at 227.965,-178.435 h0.75
  text "4" at 237.49,-178.435 h0.75
  text "CGD-15SG00D2" at 269.24,-178.435 h0.75
  text "SCALE" at 224.155,-182.88 h0.75
  text "DATE" at 247.65,-182.88 h0.75
  text "SHEET" at 288.925,-182.88 h0.75
  text "1 OF 1" at 299.72,-186.055 h0.75
  text "1 = 1" at 226.06,-186.69 h0.75
  text "7-2-17" at 252.73,-186.69 h0.75
Route Tool Path:
  lines w1: 21.49,2 21.49,9.75 ; 25.5,0 25.5,3.75 ; 25.5,8.25 25.5,11.25
ASSEMBLY_NOTES:
  lines w0.051: 45.288,7.62 45.339,7.62
  text "NOTES:" at 129.616,-13.696 h0.75
  text "NOTES:" at 129.616,-13.696 h0.75
  text "1. FABRICATE PER IPC-600, CLASS II" at 128.346,-20.046 h0.75
  text "1. FABRICATE PER IPC-600, CLASS II" at 128.346,-20.046 h0.75
  text "2. MATERIAL:" at 128.346,-26.396 h0.75
  text "2. MATERIAL:" at 128.346,-26.396 h0.75
  text "1 OZ. CU INTERNAL" at 137.236,-31.476 h0.75
  text "1 OZ. CU INTERNAL" at 137.236,-31.476 h0.75
  text "1 OZ. CU EXTERNAL" at 137.236,-36.556 h0.75
  text "1 OZ. CU EXTERNAL" at 137.236,-36.556 h0.75
  text "BASE LAMINATE FR4" at 137.236,-41.636 h0.75
  text "BASE LAMINATE FR4" at 137.236,-41.636 h0.75
  text "3. TOTAL PCB THICKNESS AFTER PLATING: 0.062 +/- 10%" at 128.346,-47.986 h0.75
  text "3. TOTAL PCB THICKNESS AFTER PLATING: 0.062 +/- 10%" at 128.346,-47.986 h0.75
  text "4. FINISH: IMMERSION SILVER PER IPC-4553" at 128.613,-53.891 h0.75
  text "(5-16 MICRO INCH THICKNESS REFERENCE)" at 162.979,-59.479 h0.75
  text "5. SOLDERMASK BOTH SIDES USING PHOTO IMAGABLE" at 128.346,-66.02 h0.75
  text "5. SOLDERMASK BOTH SIDES USING PHOTO IMAGABLE" at 128.346,-66.02 h0.75
  text "PROCESS.  SMOBC.  COLOR GREEN." at 138.506,-71.1 h0.75
  text "PROCESS.  SMOBC.  COLOR GREEN." at 138.506,-71.1 h0.75
  text "6. SILKSCREEN BOTH SIDES OF PCB USING NON-CONDUCTIVE" at 128.346,-77.45 h0.75
  text "6. SILKSCREEN BOTH SIDES OF PCB USING NON-CONDUCTIVE" at 128.346,-77.45 h0.75
  text "INK, COLOR WHITE." at 138.506,-82.53 h0.75
  text "INK, COLOR WHITE." at 138.506,-82.53 h0.75
  text "7. GERBER ARTWORK PROVIDED.  NO ALTERATIONS TO" at 128.346,-88.88 h0.75
  text "7. GERBER ARTWORK PROVIDED.  NO ALTERATIONS TO" at 128.346,-88.88 h0.75
  text "GERBER FILES WITHOUT PRIOR CONSENT." at 137.236,-93.96 h0.75
  text "GERBER FILES WITHOUT PRIOR CONSENT." at 137.236,-93.96 h0.75
  text "8. ALL DIMENSIONS ARE IN INCHES. TOLERANCES ARE:" at 128.346,-101.58 h0.75
  text "8. ALL DIMENSIONS ARE IN INCHES. TOLERANCES ARE:" at 128.346,-101.58 h0.75
  text ".XX +/- 0.10" at 134.696,-106.66 h0.75
  text ".XX +/- 0.10" at 134.696,-106.66 h0.75
  text ".XXX +/- 0.005" at 134.696,-111.74 h0.75
  text ".XXX +/- 0.005" at 134.696,-111.74 h0.75
  text "9. ALL HOLES TO BE +/- .003 UNLESS OTHERWISE SPECIFIED." at 128.346,-119.36 h0.75
  text "9. ALL HOLES TO BE +/- .003 UNLESS OTHERWISE SPECIFIED." at 128.346,-119.36 h0.75
  text "HOLE SIZES ARE GIVEN AFTER PLATING.  PLATED THRU" at 137.236,-124.44 h0.75
  text "HOLE SIZES ARE GIVEN AFTER PLATING.  PLATED THRU" at 137.236,-124.44 h0.75
  text "HOLES SHALL HAVE A MIN. OF .001 CU." at 137.236,-129.52 h0.75
  text "HOLES SHALL HAVE A MIN. OF .001 CU." at 137.236,-129.52 h0.75
  text "10. REMOVE ALL BURRS AN BREAK SHARP EDGES .015 MAX." at 124.536,-137.14 h0.75
  text "10. REMOVE ALL BURRS AN BREAK SHARP EDGES .015 MAX." at 124.536,-137.14 h0.75
DRAWING_ORIGIN:
  lines w0.025: -0.635,0 0.635,0 ; 0,-0.635 0,0.635
Bottom Assembly:
  text "1" at 46.18,14.958 h0.75 r90
Drill Drawing:
  lines w0.254: 1.259,29.737 2.953,29.737 2.106,28.044 1.259,29.737 ; 1.259,31.854 2.106,32.277 2.953,31.854 2.529,32.701 2.953,33.547 2.106,33.124 1.259,33.547 1.683,32.701 1.259,31.854 ; 1.259,35.664 2.953,35.664 2.953,37.357 1.259,37.357 1.259,35.664
  lines w0.381: -0.259,26.901 200.701,26.901 ; -0.259,38.331 200.701,38.331 ; 13.733,23.091 13.733,42.141 ; 27.445,23.091 27.445,42.141 ; 55.123,23.091 55.123,42.141 ; 67.972,23.091 67.972,42.141 ; 86.611,23.091 86.611,42.141 ; 116.828,23.091 116.828,42.141 ; 131.81,23.091 131.81,42.141 ; 165.684,23.091 165.684,42.141 ; -0.259,23.091 200.701,23.091 200.701,42.141 -0.259,42.141 -0.259,23.091
  text "Symbol" at 2.027,39.474 h1.83
  text "Count" at 14.876,39.474 h1.83
  text "Hole Size" at 28.588,39.474 h1.83
  text "Plated" at 56.266,39.474 h1.83
  text "Hole Type" at 69.115,39.474 h1.83
  text "Drill Layer Pair" at 87.754,39.474 h1.83
  text "Via/Pad" at 117.971,39.474 h1.83
  text "Hole Tolerance (+)" at 132.953,39.474 h1.83
  text "Hole Tolerance (-)" at 166.827,39.474 h1.83
  text "36" at 14.876,35.664 h1.52
  text "0.305mm (12.00mil)" at 28.588,35.664 h1.52
  text "PTH" at 56.266,35.664 h1.52
  text "Round" at 69.115,35.664 h1.52
  text "TOP - BOTTOM" at 87.754,35.664 h1.52
  text "Via" at 117.971,35.664 h1.52
  text "0.076mm (3.00mil)" at 132.953,35.664 h1.52
  text "0.076mm (3.00mil)" at 166.827,35.664 h1.52
  text "6" at 14.876,31.854 h1.52
  text "1.020mm (40.16mil)" at 28.588,31.854 h1.52
  text "PTH" at 56.266,31.854 h1.52
  text "Round" at 69.115,31.854 h1.52
  text "TOP - BOTTOM" at 87.754,31.854 h1.52
  text "Pad" at 117.971,31.854 h1.52
  text "0.076mm (3.00mil)" at 132.953,31.854 h1.52
  text "0.076mm (3.00mil)" at 166.827,31.854 h1.52
  text "2" at 14.876,28.044 h1.52
  text "1.143mm (45.00mil)" at 28.588,28.044 h1.52
  text "PTH" at 56.266,28.044 h1.52
  text "Round" at 69.115,28.044 h1.52
  text "TOP - BOTTOM" at 87.754,28.044 h1.52
  text "Pad" at 117.971,28.044 h1.52
  text "0.076mm (3.00mil)" at 132.953,28.044 h1.52
  text "0.076mm (3.00mil)" at 166.827,28.044 h1.52
  text "44 Total" at 14.876,24.234 h1.52

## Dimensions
0,0 to 2.222,5.08 on DIMENSION
47.625,0 to 45.339,7.62 on DIMENSION
0,0 to 2.222,5.08 on DIMENSION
